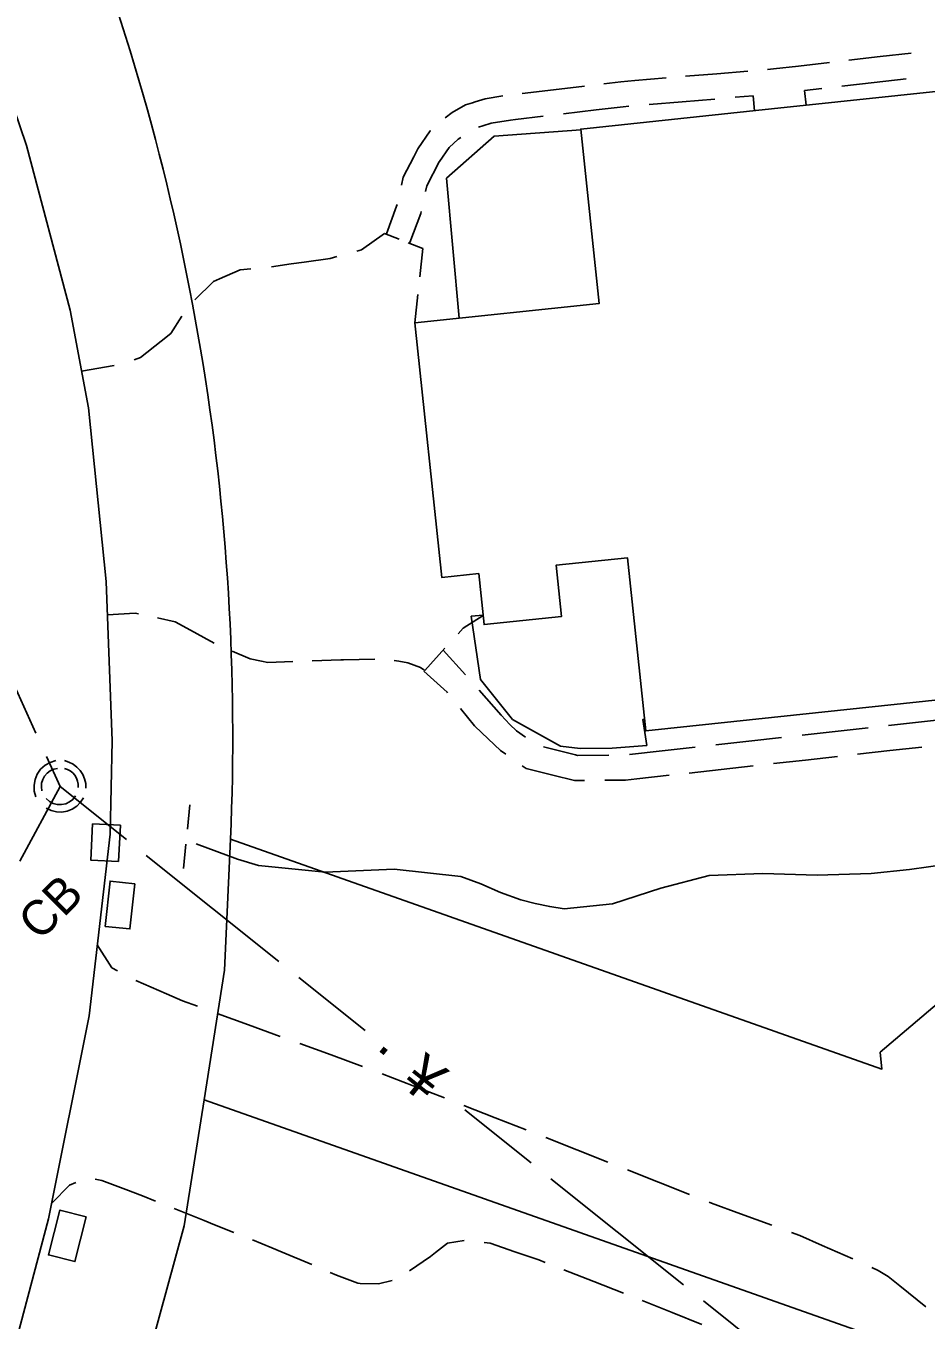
# Model space of a CAD drawing. Extents: x 2443269 to 2494951, y 591171 to 622130.
# Drawn here: x 2462283.1 to 2462389.1, y 603685.7 to 603838.1 of the extents above; entities that cross this region are included whole.
import ezdxf

# ---------------------------------------------------------------- set-up
doc = ezdxf.new("R2010")
doc.units = 0
for name, color, linetype in [('SURVEY - CENTERLINE - Existing Roads', 7, 'Continuous'), ('SURVEY - DRAINAGE - Bridge Deck with Text', 7, 'Continuous'), ('SURVEY - DRAINAGE - Bridges', 7, 'Continuous'), ('SURVEY - DRAINAGE - Natural Features', 7, 'Continuous'), ('SURVEY - DRAINAGE - Storm Sewer', 7, 'Continuous'), ('SURVEY - NON-TRANSPORTATION - Buildings', 7, 'Continuous'), ('SURVEY - NON-TRANSPORTATION - Features', 7, 'Continuous'), ('SURVEY - PROPERTY - Property Lines', 7, 'Continuous'), ('SURVEY - PROPERTY - ROW Lines', 7, 'Continuous'), ('SURVEY - TRANSPORTATION - Features', 7, 'Continuous'), ('SURVEY - TRANSPORTATION - Roads', 7, 'Continuous'), ('SURVEY - UTILITIES - Sanitary Sewer with Text', 7, 'Continuous')]:
    doc.layers.add(name, color=color, linetype=linetype)

# ---------------------------------------------------------------- blocks, each defined once
blk = doc.blocks.new('xmh')
at = {"layer": 'SURVEY - CENTERLINE - Existing Roads'}
for p, q in [((-2.286, 2.034), (-2.684, 1.466)), ((-1.773, 2.501), (-2.286, 2.034)), ((-2.286, 2.034), (-2.286, 2.034)), ((-1.525, 1.574), (-1.822, 1.23)), ((-1.171, 2.844), (-1.773, 2.501)), ((-1.773, 2.501), (-1.773, 2.501)), ((-1.161, 1.847), (-1.525, 1.574)), ((-1.525, 1.574), (-1.525, 1.574)), ((-0.508, 3.048), (-1.171, 2.844)), ((-1.171, 2.844), (-1.171, 2.844)), ((-0.748, 2.036), (-1.161, 1.847)), ((-1.161, 1.847), (-1.161, 1.847)), ((-0.304, 2.133), (-0.748, 2.036)), ((-0.748, 2.036), (-0.748, 2.036)), ((1.042, 2.883), (0.508, 3.048)), ((0.864, 2.014), (0.508, 2.133)), ((1.194, 1.835), (0.864, 2.014)), ((0.864, 2.014), (0.864, 2.014)), ((1.539, 2.628), (1.042, 2.883)), ((1.042, 2.883), (1.042, 2.883)), ((1.487, 1.599), (1.194, 1.835)), ((1.194, 1.835), (1.194, 1.835)), ((1.734, 1.316), (1.487, 1.599)), ((1.487, 1.599), (1.487, 1.599)), ((1.985, 2.291), (1.539, 2.628)), ((1.539, 2.628), (1.539, 2.628)), ((2.366, 1.882), (1.985, 2.291)), ((1.985, 2.291), (1.985, 2.291)), ((2.671, 1.413), (2.366, 1.882)), ((2.366, 1.882), (2.366, 1.882)), ((-2.948, 0.825), (-3.065, 0.141)), ((-3.065, 0.141), (-3.065, 0.141)), ((-3.065, 0.141), (-3.03, -0.551)), ((-2.684, 1.466), (-2.948, 0.825)), ((-2.948, 0.825), (-2.948, 0.825)), ((-2.684, 1.466), (-2.684, 1.466)), ((-2.167, 0.395), (-2.198, -0.058)), ((-2.039, 0.831), (-2.167, 0.395)), ((-2.167, 0.395), (-2.167, 0.395)), ((-1.822, 1.23), (-2.039, 0.831)), ((-2.039, 0.831), (-2.039, 0.831)), ((-1.822, 1.23), (-1.822, 1.23)), ((1.927, 0.994), (1.734, 1.316)), ((1.734, 1.316), (1.734, 1.316)), ((2.061, 0.643), (1.927, 0.994)), ((1.927, 0.994), (1.927, 0.994)), ((2.13, 0.274), (2.061, 0.643)), ((2.061, 0.643), (2.061, 0.643)), ((2.133, -0.101), (2.13, 0.274)), ((2.13, 0.274), (2.13, 0.274)), ((2.89, 0.899), (2.671, 1.413)), ((2.671, 1.413), (2.671, 1.413)), ((3.017, 0.354), (2.89, 0.899)), ((2.89, 0.899), (2.89, 0.899)), ((3.048, -0.203), (3.017, 0.354)), ((3.017, 0.354), (3.017, 0.354)), ((-3.03, -0.551), (-3.03, -0.551)), ((-3.03, -0.551), (-2.844, -1.219)), ((-2.198, -0.058), (-2.198, -0.058)), ((-2.198, -0.058), (-2.133, -0.508)), ((-1.625, -1.422), (-1.25, -1.756)), ((1.125, -1.825), (1.518, -1.512)), ((1.518, -1.512), (1.828, -1.117)), ((1.518, -1.512), (1.518, -1.512)), ((2.403, -1.862), (2.743, -1.32)), ((-1.625, -2.54), (-1.054, -2.827)), ((-1.25, -1.756), (-1.25, -1.756)), ((-1.25, -1.756), (-0.808, -1.995)), ((-1.054, -2.827), (-1.054, -2.827)), ((-1.054, -2.827), (-0.436, -2.988)), ((-0.808, -1.995), (-0.808, -1.995)), ((-0.808, -1.995), (-0.323, -2.125)), ((-0.436, -2.988), (-0.436, -2.988)), ((-0.436, -2.988), (0.202, -3.016)), ((-0.323, -2.125), (-0.323, -2.125)), ((-0.323, -2.125), (0.178, -2.14)), ((0.178, -2.14), (0.67, -2.038)), ((0.178, -2.14), (0.178, -2.14)), ((0.202, -3.016), (0.832, -2.91)), ((0.202, -3.016), (0.202, -3.016)), ((0.67, -2.038), (1.125, -1.825)), ((0.67, -2.038), (0.67, -2.038)), ((0.832, -2.91), (1.426, -2.675)), ((0.832, -2.91), (0.832, -2.91)), ((1.125, -1.825), (1.125, -1.825)), ((1.426, -2.675), (1.958, -2.32)), ((1.426, -2.675), (1.426, -2.675)), ((1.958, -2.32), (2.403, -1.862)), ((1.958, -2.32), (1.958, -2.32)), ((2.403, -1.862), (2.403, -1.862))]:
    blk.add_line(p, q, dxfattribs=at)

msp = doc.modelspace()

# ---------------------------------------------------------------- linework, layer by layer
at = {"layer": 'SURVEY - DRAINAGE - Bridges'}
for p, q in [((2462302.142, 603743.508), (2462302.437, 603746.355)), ((2462302.437, 603746.355), (2462302.437, 603746.355)), ((2462301.663, 603738.882), (2462301.958, 603741.729))]:
    msp.add_line(p, q, dxfattribs=at)
at = {"layer": 'SURVEY - DRAINAGE - Natural Features'}
msp.add_lwpolyline([(2462391.63, 603739.39), (2462387.142, 603738.737), (2462382.634, 603738.281), (2462376.282, 603738.091), (2462369.891, 603738.291), (2462363.559, 603738.025), (2462357.85, 603736.562), (2462352.184, 603734.712), (2462346.508, 603734.131), (2462344.789, 603734.384), (2462343.07, 603734.751), (2462341.374, 603735.194), (2462338.999, 603736.04), (2462336.666, 603737.048), (2462334.31, 603737.927), (2462326.472, 603738.806), (2462318.369, 603738.449), (2462310.488, 603739.203), (2462308.037, 603739.981), (2462305.61, 603740.876), (2462303.182, 603741.772)], dxfattribs=at)
at = {"layer": 'SURVEY - DRAINAGE - Storm Sewer'}
msp.add_line((2462292.503, 603741.903), (2462292.503, 603741.903), dxfattribs=at)
msp.add_lwpolyline([(2462294.041, 603739.696), (2462290.764, 603739.85), (2462290.965, 603744.111), (2462294.242, 603743.956)], close=True, dxfattribs=at)
at = {"layer": 'SURVEY - NON-TRANSPORTATION - Buildings'}
msp.add_lwpolyline([(2462393.585, 603830.738), (2462395.744, 603810.374), (2462418.073, 603812.74), (2462421.246, 603782.812), (2462399.061, 603780.46), (2462401.246, 603759.856), (2462356.095, 603755.069), (2462353.933, 603775.476), (2462345.541, 603774.587), (2462346.18, 603768.557), (2462337.063, 603767.589), (2462336.426, 603773.599), (2462332.089, 603773.14), (2462328.91, 603803.133), (2462350.619, 603805.433), (2462348.444, 603825.952), (2462370.915, 603828.334)], close=True, dxfattribs=at)
at = {"layer": 'SURVEY - NON-TRANSPORTATION - Features'}
for points in [[(2462334.11, 603803.685), (2462332.631, 603820.158), (2462338.231, 603825.128), (2462348.454, 603825.863)], [(2462355.951, 603756.418), (2462355.76, 603756.424), (2462356.216, 603753.366), (2462352.155, 603753.022), (2462348.365, 603753.015), (2462346.059, 603753.284), (2462340.423, 603756.414), (2462336.65, 603761.113), (2462335.554, 603768.58), (2462336.945, 603768.717)]]:
    msp.add_lwpolyline(points, dxfattribs=at)
for points in [[(2462295.938, 603737.067), (2462295.37, 603731.743), (2462292.47, 603732.051), (2462293.037, 603737.376)], [(2462290.236, 603697.835), (2462288.894, 603692.566), (2462285.777, 603693.36), (2462287.119, 603698.629)]]:
    msp.add_lwpolyline(points, close=True, dxfattribs=at)
at = {"layer": 'SURVEY - PROPERTY - Property Lines'}
for points in [[(2462307.198, 603742.33), (2462383.905, 603715.24), (2462383.686, 603717.228), (2462487.07, 603804.942)], [(2462304.097, 603711.613), (2462436.106, 603664.991), (2462519.418, 603600.599)]]:
    msp.add_lwpolyline(points, dxfattribs=at)
at = {"layer": 'SURVEY - PROPERTY - ROW Lines'}
msp.add_line((2462307.198, 603742.33), (2462307.198, 603742.33), dxfattribs=at)
for points in [[(2462307.198, 603742.33), (2462306.511, 603726.884), (2462304.097, 603711.613)], [(2462304.097, 603711.613), (2462301.752, 603696.78), (2462297.805, 603682.29)]]:
    msp.add_lwpolyline(points, dxfattribs=at)
msp.add_arc((2462032.471, 603754.556), 275, 357.45182, 21.58064, dxfattribs=at)
at = {"layer": 'SURVEY - TRANSPORTATION - Features'}
for p, q in [((2462383.674, 603834.493), (2462387.331, 603834.914)), ((2462370.413, 603832.986), (2462371.148, 603833.048)), ((2462371.148, 603833.048), (2462374.072, 603833.385)), ((2462374.072, 603833.385), (2462377.73, 603833.807)), ((2462380.016, 603834.071), (2462383.674, 603834.493)), ((2462351.158, 603831.294), (2462353.159, 603831.529)), ((2462353.159, 603831.529), (2462354.82, 603831.669)), ((2462354.82, 603831.669), (2462358.489, 603831.979)), ((2462360.782, 603832.173), (2462364.451, 603832.483)), ((2462364.451, 603832.483), (2462368.12, 603832.792)), ((2462382.981, 603831.44), (2462386.769, 603831.877)), ((2462341.559, 603830.168), (2462345.216, 603830.597)), ((2462345.216, 603830.597), (2462348.872, 603831.026)), ((2462374.766, 603830.492), (2462376.826, 603830.73)), ((2462374.989, 603828.767), (2462374.766, 603830.492)), ((2462379.193, 603831.003), (2462382.981, 603831.44)), ((2462333.293, 603827.917), (2462334.881, 603828.796)), ((2462334.881, 603828.796), (2462335.695, 603829.058)), ((2462335.695, 603829.058), (2462336.023, 603829.164)), ((2462336.023, 603829.164), (2462337.207, 603829.528)), ((2462337.207, 603829.528), (2462339.279, 603829.856)), ((2462350.253, 603828.214), (2462353.454, 603828.589)), ((2462353.454, 603828.589), (2462354.099, 603828.644)), ((2462356.508, 603828.847), (2462360.364, 603829.173)), ((2462360.364, 603829.173), (2462364.22, 603829.499)), ((2462366.63, 603829.702), (2462368.723, 603829.879)), ((2462368.723, 603829.879), (2462368.913, 603828.12)), ((2462332.491, 603827.299), (2462333.293, 603827.917)), ((2462337.877, 603826.644), (2462340.169, 603827.006)), ((2462340.169, 603827.006), (2462340.76, 603827.1)), ((2462340.76, 603827.1), (2462344.008, 603827.481)), ((2462346.41, 603827.763), (2462350.253, 603828.214)), ((2462329.274, 603823.652), (2462330.715, 603825.752)), ((2462330.715, 603825.752), (2462330.756, 603825.789)), ((2462336.398, 603826.182), (2462336.909, 603826.345)), ((2462336.909, 603826.345), (2462337.877, 603826.644)), ((2462332.949, 603823.79), (2462334.028, 603824.754)), ((2462334.028, 603824.754), (2462334.318, 603824.978)), ((2462327.542, 603820.292), (2462328.78, 603822.692)), ((2462328.78, 603822.692), (2462329.274, 603823.652)), ((2462331.814, 603822.133), (2462332.949, 603823.79)), ((2462330.337, 603819.272), (2462331.792, 603822.091)), ((2462331.792, 603822.091), (2462331.814, 603822.133)), ((2462327.325, 603819.335), (2462327.542, 603820.292)), ((2462330.183, 603818.592), (2462330.337, 603819.272)), ((2462325.56, 603813.632), (2462326.768, 603816.87)), ((2462326.768, 603816.87), (2462326.818, 603817.091)), ((2462329.602, 603816.024), (2462329.65, 603816.233)), ((2462328.326, 603812.599), (2462329.602, 603816.024)), ((2462325.321, 603813.675), (2462322.621, 603811.733)), ((2462327.048, 603812.99), (2462325.321, 603813.675)), ((2462325.321, 603813.675), (2462325.321, 603813.675)), ((2462322.621, 603811.733), (2462322.07, 603811.582)), ((2462329.855, 603811.877), (2462328.128, 603812.562)), ((2462329.495, 603808.546), (2462329.855, 603811.877)), ((2462329.855, 603811.877), (2462329.855, 603811.877)), ((2462315.881, 603810.299), (2462314.346, 603810.086)), ((2462318.936, 603810.725), (2462315.881, 603810.299)), ((2462319.72, 603810.94), (2462318.936, 603810.725)), ((2462308.359, 603809.387), (2462305.925, 603808.339)), ((2462309.602, 603809.495), (2462308.359, 603809.387)), ((2462314.346, 603810.086), (2462312.025, 603809.737)), ((2462305.19, 603808.022), (2462302.999, 603805.833)), ((2462305.925, 603808.339), (2462305.19, 603808.022)), ((2462328.91, 603803.133), (2462329.27, 603806.464)), ((2462301.496, 603803.934), (2462300.17, 603801.864)), ((2462299.04, 603800.974), (2462296.62, 603799.068)), ((2462300.17, 603801.864), (2462299.04, 603800.974)), ((2462293.523, 603798.106), (2462289.681, 603797.448)), ((2462296.62, 603799.068), (2462295.851, 603798.791)), ((2462289.681, 603797.448), (2462289.681, 603797.448)), ((2462292.713, 603768.74), (2462296, 603768.95)), ((2462296, 603768.95), (2462296.38, 603768.868)), ((2462298.629, 603768.38), (2462300.685, 603767.933)), ((2462300.685, 603767.933), (2462302.071, 603767.177)), ((2462334.612, 603767.189), (2462336.948, 603768.681)), ((2462336.948, 603768.681), (2462336.948, 603768.681)), ((2462302.071, 603767.177), (2462305.303, 603765.412)), ((2462334.002, 603766.513), (2462334.612, 603767.189)), ((2462307.405, 603764.475), (2462309.517, 603763.557)), ((2462330.098, 603762.192), (2462332.459, 603764.805)), ((2462334.854, 603761.671), (2462332.257, 603764.58)), ((2462332.257, 603764.58), (2462332.257, 603764.58)), ((2462309.517, 603763.557), (2462310.867, 603763.274)), ((2462310.867, 603763.274), (2462311.597, 603763.12)), ((2462311.597, 603763.12), (2462314.532, 603763.235)), ((2462316.832, 603763.324), (2462320.19, 603763.455)), ((2462320.19, 603763.455), (2462320.512, 603763.46)), ((2462320.512, 603763.46), (2462324.194, 603763.522)), ((2462326.487, 603763.357), (2462327.027, 603763.304)), ((2462327.027, 603763.304), (2462328.07, 603763.107)), ((2462328.07, 603763.107), (2462329.583, 603762.553)), ((2462329.583, 603762.553), (2462329.966, 603762.284)), ((2462329.966, 603762.284), (2462330.098, 603762.192)), ((2462332.703, 603759.62), (2462329.97, 603762.12)), ((2462329.97, 603762.12), (2462329.97, 603762.12)), ((2462339.074, 603756.942), (2462336.477, 603759.852)), ((2462332.764, 603759.544), (2462332.703, 603759.62)), ((2462335.925, 603755.673), (2462334.267, 603757.704)), ((2462340.078, 603755.817), (2462339.074, 603756.942)), ((2462336.783, 603754.864), (2462335.925, 603755.673)), ((2462340.872, 603755.069), (2462340.078, 603755.817)), ((2462382.267, 603755.437), (2462378.391, 603755.005)), ((2462388.566, 603756.14), (2462384.69, 603755.708)), ((2462392.442, 603756.573), (2462388.566, 603756.14)), ((2462338.999, 603752.776), (2462336.783, 603754.864)), ((2462341.935, 603754.319), (2462340.872, 603755.069)), ((2462368.216, 603753.869), (2462364.34, 603753.436)), ((2462372.092, 603754.302), (2462368.216, 603753.869)), ((2462378.391, 603755.005), (2462374.515, 603754.572)), ((2462339.618, 603752.34), (2462338.999, 603752.776)), ((2462347.839, 603752.247), (2462344.054, 603753.191)), ((2462348.073, 603752.189), (2462347.839, 603752.247)), ((2462351.731, 603752.215), (2462348.073, 603752.189)), ((2462358.041, 603752.733), (2462354.165, 603752.3)), ((2462361.917, 603753.166), (2462358.041, 603752.733)), ((2462384.809, 603752.749), (2462381.031, 603752.327)), ((2462388.587, 603753.171), (2462384.809, 603752.749)), ((2462341.997, 603750.663), (2462341.56, 603750.971)), ((2462345.166, 603749.871), (2462341.997, 603750.663)), ((2462368.753, 603750.957), (2462364.975, 603750.535)), ((2462374.892, 603751.642), (2462371.114, 603751.22)), ((2462378.67, 603752.064), (2462374.892, 603751.642)), ((2462347.719, 603749.233), (2462345.166, 603749.871)), ((2462348.889, 603749.241), (2462347.719, 603749.233)), ((2462353.69, 603749.275), (2462351.265, 603749.258)), ((2462355.058, 603749.428), (2462353.69, 603749.275)), ((2462358.836, 603749.85), (2462355.058, 603749.428)), ((2462364.975, 603750.535), (2462361.197, 603750.113)), ((2462291.525, 603729.869), (2462293.244, 603727.176)), ((2462293.244, 603727.176), (2462293.889, 603726.808)), ((2462296.064, 603725.663), (2462299.68, 603724.104)), ((2462299.68, 603724.104), (2462301.564, 603723.291)), ((2462301.564, 603723.291), (2462303.335, 603722.644)), ((2462305.647, 603721.8), (2462309.346, 603720.449)), ((2462309.346, 603720.449), (2462313.044, 603719.097)), ((2462315.356, 603718.253), (2462319.055, 603716.902)), ((2462319.055, 603716.902), (2462322.753, 603715.551)), ((2462325.061, 603714.695), (2462328.73, 603713.265)), ((2462328.73, 603713.265), (2462332.399, 603711.835)), ((2462334.692, 603710.941), (2462338.361, 603709.512)), ((2462338.361, 603709.512), (2462342.03, 603708.082)), ((2462344.319, 603707.178), (2462347.98, 603705.729)), ((2462347.98, 603705.729), (2462351.642, 603704.28)), ((2462288.244, 603701.556), (2462289, 603701.88)), ((2462291.291, 603702.255), (2462292.05, 603702.123)), ((2462292.05, 603702.123), (2462294.868, 603701.065)), ((2462353.93, 603703.374), (2462357.591, 603701.924)), ((2462357.591, 603701.924), (2462361.253, 603700.475)), ((2462286.164, 603699.453), (2462288.244, 603701.556)), ((2462294.868, 603701.065), (2462296.847, 603700.322)), ((2462296.847, 603700.322), (2462298.393, 603699.699)), ((2462363.541, 603699.569), (2462363.844, 603699.449)), ((2462363.844, 603699.449), (2462367.235, 603698.207)), ((2462300.585, 603698.817), (2462304.092, 603697.404)), ((2462304.092, 603697.404), (2462305.311, 603696.913)), ((2462367.235, 603698.207), (2462370.933, 603696.852)), ((2462305.311, 603696.913), (2462307.6, 603695.995)), ((2462373.244, 603696.006), (2462374.215, 603695.65)), ((2462309.793, 603695.116), (2462312.093, 603694.193)), ((2462331.354, 603693.637), (2462332.762, 603694.741)), ((2462332.762, 603694.741), (2462334.732, 603695.031)), ((2462337.073, 603694.813), (2462337.772, 603694.718)), ((2462337.772, 603694.718), (2462340.684, 603693.728)), ((2462374.215, 603695.65), (2462376.872, 603694.48)), ((2462376.872, 603694.48), (2462380.476, 603692.894)), ((2462312.093, 603694.193), (2462313.293, 603693.685)), ((2462313.293, 603693.685), (2462316.774, 603692.211)), ((2462328.264, 603691.46), (2462330.764, 603693.173)), ((2462330.764, 603693.173), (2462331.354, 603693.637)), ((2462340.684, 603693.728), (2462343.523, 603692.763)), ((2462343.523, 603692.763), (2462344.25, 603692.476)), ((2462318.95, 603691.29), (2462319.688, 603690.978)), ((2462346.449, 603691.61), (2462349.966, 603690.225)), ((2462382.713, 603691.868), (2462383.447, 603691.529)), ((2462383.447, 603691.529), (2462384.648, 603690.808)), ((2462319.688, 603690.978), (2462322.194, 603690.01)), ((2462322.194, 603690.01), (2462322.487, 603690.004)), ((2462322.487, 603690.004), (2462324.632, 603689.958)), ((2462324.632, 603689.958), (2462326.227, 603690.319)), ((2462349.966, 603690.225), (2462353.484, 603688.839)), ((2462384.648, 603690.808), (2462385.993, 603689.722)), ((2462385.993, 603689.722), (2462389.057, 603687.249)), ((2462355.683, 603687.973), (2462358.041, 603687.044)), ((2462358.041, 603687.044), (2462359.197, 603686.581)), ((2462359.197, 603686.581), (2462362.706, 603685.173))]:
    msp.add_line(p, q, dxfattribs=at)
at = {"layer": 'SURVEY - TRANSPORTATION - Roads'}
for points in [[(2462421.147, 604012.27), (2462393.434, 603988.376), (2462358.818, 603958.232), (2462330.56, 603933.78), (2462305.951, 603912.733), (2462286.066, 603895.45), (2462282.798, 603892.687), (2462276.994, 603887.625), (2462274.491, 603885.233), (2462272.043, 603881.26), (2462270.928, 603879.767), (2462268.848, 603872.497), (2462268.815, 603867.274), (2462270.616, 603859.961), (2462276.978, 603842.231), (2462283.195, 603824.026), (2462288.346, 603804.623), (2462290.488, 603793.124), (2462292.562, 603772.658), (2462293.277, 603753.921), (2462293.034, 603742.91)], [(2462293.034, 603742.91), (2462290.554, 603721.5), (2462285.8, 603697.615), (2462278.815, 603671.385)]]:
    msp.add_lwpolyline(points, dxfattribs=at)
at = {"layer": 'SURVEY - UTILITIES - Sanitary Sewer with Text'}
for p, q in [((2462276.042, 603773.027), (2462284.296, 603754.81)), ((2462285.534, 603752.077), (2462287.144, 603748.525)), ((2462287.144, 603748.525), (2462282.402, 603739.72)), ((2462287.144, 603748.525), (2462294.953, 603742.279)), ((2462297.296, 603740.406), (2462312.916, 603727.914)), ((2462315.259, 603726.041), (2462323.069, 603719.795)), ((2462334.783, 603710.427), (2462342.593, 603704.181)), ((2462344.936, 603702.308), (2462360.556, 603689.816)), ((2462362.899, 603687.943), (2462370.708, 603681.697))]:
    msp.add_line(p, q, dxfattribs=at)

# ---------------------------------------------------------------- block references
msp.add_blockref('xmh', (2462287.144, 603748.525), dxfattribs=at)

# ---------------------------------------------------------------- texts
at = {"layer": 'SURVEY - DRAINAGE - Bridge Deck with Text'}
msp.add_text('CB', height=4.101, rotation=45, dxfattribs=at).set_placement((2462284.75, 603730.21))
at = {"layer": 'SURVEY - UTILITIES - Sanitary Sewer with Text'}
for s, p in [('·', (2462323.134, 603716.542)), ('¥', (2462327.039, 603713.419))]:
    msp.add_text(s, height=5, rotation=321.35016, dxfattribs=at).set_placement(p)

doc.saveas('drawing.dxf')
